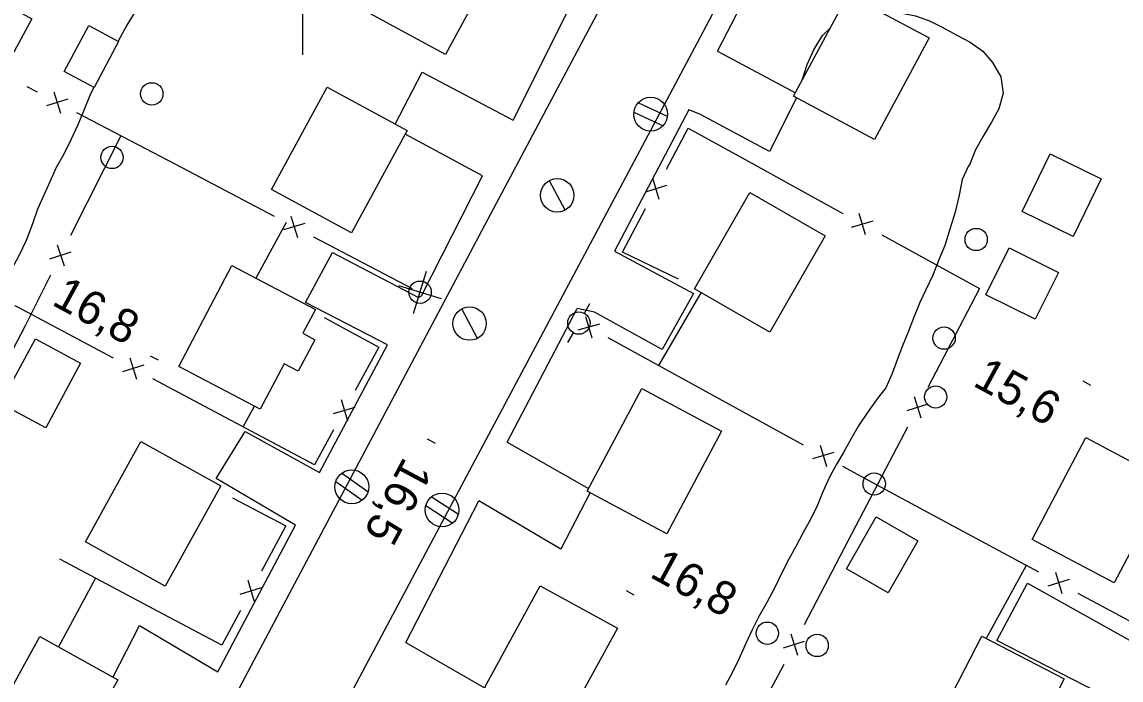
# Model space of a CAD drawing. Extents: x 219136 to 222520, y 5421589 to 5424530.
# Drawn here: x 220374.8 to 220473.5, y 5423733.9 to 5423792.9 of the extents above; entities that cross this region are included whole.
import ezdxf

# ---------------------------------------------------------------- set-up
doc = ezdxf.new("R2010")
doc.units = 0
for name, color, linetype in [('Level 19', 7, 'Continuous'), ('Level 2', 7, 'Continuous'), ('Level 21', 7, 'Continuous'), ('Level 3', 7, 'Continuous'), ('Level 31', 7, 'Continuous'), ('Level 36', 7, 'Continuous'), ('Level 37', 7, 'Continuous'), ('Level 61', 7, 'Continuous')]:
    doc.layers.add(name, color=color, linetype=linetype)

msp = doc.modelspace()

# ---------------------------------------------------------------- linework, layer by layer
at = {"layer": 'Level 19'}
for points in [[(220437.24, 5423790.31), (220444.24, 5423786.59)], [(220408.33, 5423783.77), (220410.75, 5423788.44), (220418.91, 5423784.14)], [(220444.33, 5423786.13), (220441.92, 5423781.31), (220435.65, 5423784.68), (220434.67, 5423785.04)], [(220416.17, 5423779.13), (220409.21, 5423782.86)], [(220407.63, 5423763.98), (220400.28, 5423767.78), (220402.69, 5423772.26), (220410.42, 5423768.23), (220410.67, 5423768.38)], [(220428, 5423772.38), (220435.09, 5423768.6), (220432.28, 5423763.55), (220426.21, 5423766.91), (220424.65, 5423767.23)], [(220399.38, 5423747.82), (220392.27, 5423752), (220394.85, 5423756.2), (220401.53, 5423752.53)], [(220418.36, 5423755.27), (220425.67, 5423751.09)], [(220425.82, 5423750.73), (220423.19, 5423745.66), (220415.82, 5423749.99)], [(220475.83, 5423730.53), (220462.3, 5423737.48), (220465.07, 5423742.62), (220477.26, 5423735.8), (220478.94, 5423735.83), (220479.81, 5423736.58)], [(220383.02, 5423734.2), (220385.38, 5423738.82), (220392.41, 5423734.66)], [(220409.29, 5423737.29), (220416.35, 5423733.24), (220413.66, 5423728.12), (220406.71, 5423732.16)]]:
    msp.add_lwpolyline(points, dxfattribs=at)
at = {"layer": 'Level 2'}
for points in [[(220394.96, 5423812.87), (220394.68, 5423811.61), (220394.18, 5423810.23), (220393.69, 5423808.96), (220392.99, 5423807.93), (220392.09, 5423806.74), (220391.37, 5423805.64), (220390.62, 5423804.4), (220390.03, 5423803.12), (220389.43, 5423801.96), (220388.77, 5423800.87), (220388.11, 5423799.76), (220387.48, 5423798.42), (220386.89, 5423797.26), (220386.31, 5423796.12), (220385.69, 5423794.98), (220384.96, 5423793.81), (220384.25, 5423792.65), (220383.66, 5423791.54), (220383.47, 5423791.21)], [(220451.81, 5423793.87), (220452.24, 5423793.89), (220453.77, 5423793.72), (220455.01, 5423793.49), (220456.28, 5423793.04), (220457.41, 5423792.46), (220458.73, 5423791.75), (220459.9, 5423791.12), (220461.04, 5423790.31), (220461.91, 5423789.31), (220462.67, 5423788.02), (220462.87, 5423786.55), (220462.48, 5423785.14), (220461.84, 5423783.94)], [(220444.85, 5423787.72), (220445.28, 5423789.12), (220445.88, 5423790.42), (220446.65, 5423791.73), (220447.33, 5423792.35)], [(220381.27, 5423787.07), (220380.98, 5423786.49), (220380.4, 5423785.07), (220379.85, 5423783.7), (220379.24, 5423782.42), (220378.6, 5423781.09), (220377.89, 5423779.87), (220377.33, 5423778.6), (220376.81, 5423777.39), (220376.23, 5423776.14), (220375.77, 5423774.82), (220375.21, 5423773.33), (220374.54, 5423771.97), (220373.95, 5423770.86), (220373.16, 5423769.6), (220372.52, 5423768.49), (220371.85, 5423767.15), (220371.08, 5423765.8), (220370.37, 5423764.55), (220369.62, 5423763.38), (220368.95, 5423762.13), (220368.42, 5423760.97), (220367.66, 5423759.62)], [(220461.84, 5423783.94), (220461.09, 5423782.69), (220460.38, 5423781.48), (220459.88, 5423780.18), (220459.73, 5423779.98), (220459.19, 5423778.8), (220458.93, 5423777.4), (220458.56, 5423775.88), (220458.13, 5423774.43), (220457.65, 5423772.9), (220457.17, 5423771.74), (220456.55, 5423770.22), (220455.93, 5423768.91), (220455.39, 5423767.79), (220454.84, 5423766.36), (220454.33, 5423765.05), (220453.85, 5423763.88), (220453.36, 5423762.63), (220452.91, 5423761.42), (220452.34, 5423760.13), (220451.58, 5423759.13), (220450.71, 5423757.93), (220449.88, 5423756.71), (220449.22, 5423755.53), (220448.54, 5423754.33), (220447.9, 5423753.21), (220447.28, 5423752.12), (220446.69, 5423750.79), (220446.21, 5423749.62), (220445.62, 5423748.39), (220444.91, 5423747.09), (220444.27, 5423745.9), (220443.64, 5423744.75), (220442.96, 5423743.42), (220442.39, 5423742.23), (220441.67, 5423740.87), (220440.96, 5423739.62), (220440.36, 5423738.44), (220439.75, 5423737.13), (220439.15, 5423735.79), (220438.56, 5423734.56), (220437.96, 5423733.46)]]:
    msp.add_lwpolyline(points, dxfattribs=at)
at = {"layer": 'Level 21'}
for points in [[(220487.03, 5423888.54), (220465.15, 5423847.31), (220435.66, 5423791.5), (220395.53, 5423716.17), (220395, 5423713.83), (220395.18, 5423712.12), (220395.79, 5423710.5), (220396.86, 5423709.12), (220398.43, 5423708.11), (220421.78, 5423695.72), (220446.77, 5423682.53), (220448.04, 5423682.22), (220450.48, 5423682.48), (220452.12, 5423683.37), (220453.44, 5423684.6), (220454.56, 5423686.36), (220498.61, 5423769.69), (220524.31, 5423818.83)], [(220362.68, 5423814.15), (220332.84, 5423757.85), (220331.21, 5423754.5), (220330.74, 5423752.63), (220331.07, 5423750.02), (220331.84, 5423747.36), (220333.26, 5423744.43), (220335.1, 5423742.11), (220337.36, 5423740.62), (220380.15, 5423717.86), (220382.03, 5423717.38), (220383.72, 5423717.55), (220385.46, 5423718.3), (220386.94, 5423719.63), (220388.05, 5423721.33), (220416.41, 5423774.78), (220454.01, 5423845.53)], [(220437.24, 5423790.31), (220443.65, 5423802.7)], [(220418.91, 5423784.14), (220424.36, 5423795)], [(220434.67, 5423785.04), (220428, 5423772.38)], [(220410.67, 5423768.38), (220416.17, 5423779.13)], [(220418.36, 5423755.27), (220424.65, 5423767.23)], [(220401.53, 5423752.53), (220407.63, 5423763.98)], [(220409.29, 5423737.29), (220415.82, 5423749.99)], [(220392.41, 5423734.66), (220399.38, 5423747.82)]]:
    msp.add_lwpolyline(points, dxfattribs=at)
at = {"layer": 'Level 3'}
for p, q in [((220386.35, 5423763.01), (220387.05, 5423762.63)), ((220470.02, 5423760.75), (220470.72, 5423760.37)), ((220411.2, 5423755.54), (220411.9, 5423755.16)), ((220429.04, 5423741.95), (220429.74, 5423741.57))]:
    msp.add_line(p, q, dxfattribs=at)
at = {"layer": 'Level 31'}
for points in [[(220375.73, 5423793.21), (220370.38, 5423783.39), (220368.71, 5423784.29), (220365.38, 5423778.15), (220357.32, 5423782.54), (220360.72, 5423788.8), (220361.69, 5423788.27), (220366.84, 5423797.75), (220365.76, 5423798.34), (220369.15, 5423804.59), (220377.26, 5423800.18), (220373.99, 5423794.16)], [(220417.75, 5423799.08), (220412.85, 5423790.02), (220405.72, 5423793.88), (220410.62, 5423802.94)], [(220456.23, 5423791.51), (220451.34, 5423782.38), (220444.07, 5423786.27), (220448.96, 5423795.4)], [(220378.62, 5423788.49), (220380.83, 5423792.62), (220383.5, 5423791.19), (220381.3, 5423787.06)], [(220409.39, 5423783.19), (220404.4, 5423774.02), (220397.23, 5423777.92), (220402.22, 5423787.09)], [(220469.17, 5423773.71), (220464.59, 5423775.94), (220467.1, 5423781.11), (220471.68, 5423778.88)], [(220446.89, 5423773.77), (220441.94, 5423765.12), (220435.18, 5423768.99), (220440.13, 5423777.65)], [(220465.74, 5423766.27), (220461.31, 5423768.47), (220463.4, 5423772.67), (220467.83, 5423770.47)], [(220388.91, 5423762.05), (220393.67, 5423771.09), (220401.16, 5423767.15), (220400.03, 5423765.02), (220401.12, 5423764.44), (220399.63, 5423761.61), (220398.36, 5423762.28), (220396.22, 5423758.2)], [(220372.91, 5423758.73), (220376.04, 5423764.53), (220380.09, 5423762.35), (220376.97, 5423756.55)], [(220437.6, 5423756.25), (220432.71, 5423747.05), (220425.55, 5423750.87), (220430.44, 5423760.06)], [(220392.67, 5423751.35), (220387.69, 5423742.35), (220380.52, 5423746.32), (220385.5, 5423755.32)], [(220465.47, 5423746.53), (220470.28, 5423755.66), (220477.66, 5423751.77), (220472.85, 5423742.64)], [(220455.23, 5423746.41), (220452.57, 5423741.76), (220448.82, 5423743.91), (220451.48, 5423748.56)], [(220428.26, 5423738.57), (220423.28, 5423729.45), (220416.35, 5423733.24), (220421.32, 5423742.36)], [(220383.45, 5423733.96), (220378.18, 5423724.43), (220371.17, 5423728.3), (220376.44, 5423737.84)], [(220456.26, 5423728.75), (220460.96, 5423737.86), (220468.36, 5423734.04), (220463.66, 5423724.93)]]:
    msp.add_lwpolyline(points, close=True, dxfattribs=at)
at = {"layer": 'Level 36'}
for p, q in [((220432.75, 5423784.47), (220430.12, 5423785.69)), ((220429.75, 5423784.85), (220432.38, 5423783.63)), ((220423.58, 5423776.06), (220422.16, 5423778.7)), ((220409.98, 5423766.78), (220411.13, 5423770.6)), ((220412.47, 5423768.12), (220408.65, 5423769.27)), ((220415.71, 5423764.56), (220414.29, 5423767.2)), ((220425.77, 5423767.67), (220425.29, 5423766.79)), ((220423.81, 5423764.18), (220424.31, 5423765.05)), ((220405.87, 5423750.8), (220403.51, 5423752.48)), ((220402.99, 5423751.72), (220405.35, 5423750.04)), ((220413.99, 5423748.77), (220411.56, 5423750.35)), ((220411.07, 5423749.57), (220413.5, 5423747.99))]:
    msp.add_line(p, q, dxfattribs=at)
for centre, radius in [((220386.484, 5423786.487), 1), ((220431.246, 5423784.667), 1.518), ((220382.914, 5423780.787), 1), ((220422.864, 5423777.387), 1.5), ((220460.454, 5423773.427), 1), ((220410.557, 5423768.703), 1), ((220414.994, 5423765.887), 1.5), ((220424.804, 5423765.933), 1), ((220457.574, 5423764.587), 1), ((220456.814, 5423759.307), 1), ((220404.433, 5423751.252), 1.518), ((220451.304, 5423751.507), 1), ((220412.527, 5423749.178), 1.518), ((220441.714, 5423738.127), 1), ((220446.184, 5423737.027), 1)]:
    msp.add_circle(centre, radius, dxfattribs=at)
at = {"layer": 'Level 37'}
for p, q in [((220377.7, 5423786.66), (220378.29, 5423784.75)), ((220378.95, 5423786), (220377.04, 5423785.41)), ((220432.02, 5423777.02), (220431.43, 5423778.93)), ((220432.68, 5423778.27), (220430.77, 5423777.68)), ((220450.52, 5423773.85), (220449.96, 5423775.77)), ((220400.21, 5423774.87), (220398.3, 5423774.28)), ((220398.96, 5423775.53), (220399.56, 5423773.62)), ((220449.28, 5423774.53), (220451.2, 5423775.09)), ((220377.98, 5423772.96), (220378.61, 5423771.06)), ((220377.34, 5423771.69), (220379.24, 5423772.32)), ((220426.64, 5423765.85), (220424.72, 5423765.29)), ((220425.4, 5423766.53), (220425.96, 5423764.61)), ((220385.76, 5423762.15), (220383.85, 5423761.56)), ((220384.51, 5423762.82), (220385.1, 5423760.9)), ((220403.48, 5423759.08), (220404.04, 5423757.16)), ((220454.9, 5423759.34), (220455.5, 5423757.43)), ((220402.8, 5423757.84), (220404.72, 5423758.4)), ((220454.25, 5423758.08), (220456.16, 5423758.68)), ((220446.45, 5423755), (220447.01, 5423753.08)), ((220447.69, 5423754.32), (220445.77, 5423753.76)), ((220467.56, 5423743.6), (220468.14, 5423741.68)), ((220394.42, 5423741.64), (220396.34, 5423742.22)), ((220395.09, 5423742.89), (220395.67, 5423740.98)), ((220468.81, 5423742.93), (220466.89, 5423742.35)), ((220443.15, 5423736.8), (220445.06, 5423737.4)), ((220443.81, 5423738.06), (220444.41, 5423736.15))]:
    msp.add_line(p, q, dxfattribs=at)
for points in [[(220376.22, 5423786.63), (220375.29, 5423787.12)], [(220388.63, 5423780.14), (220379.77, 5423784.78)], [(220383.7, 5423782.72), (220379.19, 5423773.79)], [(220432.66, 5423779.74), (220434.6, 5423783.41), (220439.72, 5423780.59)], [(220397.49, 5423775.5), (220388.63, 5423780.14)], [(220439.72, 5423780.59), (220448.49, 5423775.77)], [(220433.74, 5423769.86), (220428.72, 5423772.3), (220430.79, 5423776.21)], [(220398.55, 5423774.94), (220395.81, 5423769.97)], [(220451.99, 5423773.85), (220460.75, 5423769.03), (220460.75, 5423769.03)], [(220409.89, 5423769.01), (220401.03, 5423773.65)], [(220377.39, 5423770.22), (220375.11, 5423765.7), (220372.82, 5423761.33)], [(220460.75, 5423769.03), (220456.13, 5423760.16)], [(220431.97, 5423762.13), (220435.79, 5423768.64)], [(220383.04, 5423762.8), (220374.39, 5423767.38), (220374.2, 5423767.48)], [(220401.96, 5423766.43), (220406.85, 5423763.76), (220404.72, 5423759.88)], [(220436.21, 5423759.8), (220427.44, 5423764.61)], [(220395.41, 5423756.24), (220386.57, 5423760.92)], [(220444.97, 5423755), (220436.21, 5423759.8)], [(220394.69, 5423756.62), (220395.69, 5423758.48)], [(220402.8, 5423756.37), (220401.08, 5423753.23), (220395.41, 5423756.24)], [(220454.28, 5423756.61), (220449.65, 5423747.74)], [(220457.28, 5423748.32), (220451.56, 5423751.39), (220448.48, 5423753.08)], [(220393.73, 5423750.27), (220398.5, 5423747.76), (220396.32, 5423743.7)], [(220466.09, 5423743.59), (220457.28, 5423748.32)], [(220449.65, 5423747.74), (220445.03, 5423738.88)], [(220387.05, 5423740.08), (220378.22, 5423744.76)], [(220464.93, 5423744.21), (220461.36, 5423737.65)], [(220381.43, 5423743.06), (220378.12, 5423736.91)], [(220478.42, 5423736.96), (220469.61, 5423741.69)], [(220394.43, 5423740.17), (220392.76, 5423737.05), (220387.05, 5423740.08)], [(220443.18, 5423735.33), (220442.21, 5423733.46), (220438.52, 5423726.48)]]:
    msp.add_lwpolyline(points, dxfattribs=at)
at = {"layer": 'Level 61'}
msp.add_lwpolyline([(220400, 5423810), (220400, 5423800), (220400, 5423790)], dxfattribs=at)

# ---------------------------------------------------------------- texts
at = {"layer": 'Level 3'}
for s, rotation, p in [('16,8', 331.383, (220377.4, 5423767.63)), ('15,6', 331.383, (220460.05, 5423760.37)), ('16,5', 241.96198, (220409.12, 5423754.04)), ('16,8', 331.383, (220431.05, 5423743.22))]:
    msp.add_text(s, height=3, rotation=rotation, dxfattribs=at).set_placement(p)

doc.saveas('drawing.dxf')
